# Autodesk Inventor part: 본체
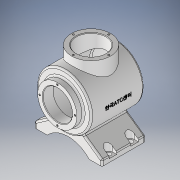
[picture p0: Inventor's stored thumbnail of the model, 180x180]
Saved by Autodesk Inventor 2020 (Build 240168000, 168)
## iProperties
Created: 2023-12
Part Number: 본체
Material: 일반
Document SubType Name: Modeling
Designer: 1강의실14
Density: 1 g/cm^3
Appearance: 기본값
Author: 1강의실14
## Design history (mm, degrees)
sketch "스케치1"
  geometry: L1 (50, 60)-(-50, 60); L2 (-50, 60)-(-50, -60); L3 (-50, -60)-(50, -60); L4 (50, -60)-(50, 60); L5 (50, 60)-(-50, -60); L6 (-50, 60)-(50, -60); L7 (0, 60)-(0, -60); L8 (0, 60)-(36, 60); L9 (36, 60)-(36, 48); L10 (36, 48)-(50, 48); L11 (36, 48)-(-16.182, 48); A1 r 113 centre (0, 53) between (-50, -48.336) and (50, -48.336); 3 further points
  constraints: 22 end point, 6 midpoint, 4 point on line, 3 perpendicular, 3 point on circle, 2 horizontal, 2 parallel, 1 centre point, 1 tangent, 1 vertical alignment
  dimensions: "d0" = 100 distance of L3.end L2.end; "d1" = 120 distance of L2.end L1.end; "d2" = 113 radius of A1; "d3" = 36 distance of L7.start L8.end; "d4" = 12 distance of L8.end L9.end
revolve "회전1" sketch "스케치1" stored, may be unused: angle "d5" = 90 deg
sketch "스케치2"
  geometry: 1 further point
feature "쉘1" dims "d9" = 7
sketch "스케치3"
  geometry: C1 r 36 at (0, 0); 1 further point
  constraints: 1 centre point, 1 coincident
  dimensions: "d10" = 72 diameter of C1
extrude "돌출1" join sketch "스케치3" distance "d11" = 12; taper "d12" = 0 deg
sketch "스케치4"
  geometry: C1 r 27 at (0, 0); 1 further point
  constraints: 1 centre point, 1 coincident
  dimensions: "d13" = 54 diameter of C1
extrude "돌출2" cut sketch "스케치4" distance "d14" = 19; taper "d15" = 0 deg
node "작업 평면2"
sketch "스케치7"
  geometry: L1 (36, 60)-(-36, 60) reference; C1 r 36 at (0, -2); C2 r 27 at (0, -2); 1 further point
  constraints: 2 centre point, 1 coincident, 1 vertical alignment
  dimensions: "d25" = 72 diameter of C1; "d26" = 54 diameter of C2; "d27" = 62 distance from line of L1 C1.centre
extrude "돌출5" join sketch "스케치7" stored distance "d28" = 19; taper "d29" = 0 deg
extrude "돌출6" cut sketch "스케치7" stored distance "d30" = 19; taper "d31" = 0 deg
node "작업 평면3"
sketch "스케치8"
  geometry: L1 (0, 0)-(0, -77); L2 (0, -77)-(-62, -77); L3 (-62, -77)-(-62, -67); L4 (-62, -67)-(-26.694, -42.278); L5 (62, -77)-(62, -67); L6 (62, -67)-(26.694, -42.278); L7 (62, -77)-(0, -77); L8 (0, -77)-(38.5, -77); L9 (0, -77)-(-38.5, -77); L10 (0, -60)-(22.364, -60); L11 (22.364, -60)-(16.943, -56.204); A1 r 52.096 centre (0, -112.096) between (38.5, -77) and (-38.5, -77); 2 further points
  constraints: 22 end point, 3 point on circle, 3 symmetric about line, 2 horizontal, 2 point on line, 2 vertical, 1 centre point, 3 other
  dimensions: "d33" = 77 distance of L1.start L1.end; "d38" = 62 distance of L1.end L2.end; "d39" = 10 distance of L2.end L3.end; "d40" = 55 deg angle of L3 L4; "d42" = 38.5 distance of L1.end L8.end; "d43" = 38.5 distance of L1.end L9.end; "d44" = 17 distance between parallel lines of L7 L10; "d45" = 52.09559 radius of A1
extrude "돌출7" join sketch "스케치8" distance "d46" = 80; taper "d47" = 0 deg
node "작업 평면4"
sketch "스케치10"
  geometry: L1 (-47, -20)-(-76.641, -20); L2 (-54, -13)-(-69.641, -13); L3 (-69.641, -27)-(-54, -27); L4 (-62, -40)-(-62, 40) reference; L5 (-38.5, -40)-(-62, -40) reference; A1 r 7 centre (-54, -20) between (-54, -27) and (-54, -13); A2 r 7 centre (-69.641, -20) between (-69.641, -13) and (-69.641, -27); 2 further points
  constraints: 8 end point, 6 point on circle, 4 tangent, 2 centre point, 2 point on line, 1 horizontal, 1 midpoint, 1 parallel
  dimensions: "d51" = 14 diameter of A2; "d52" = 8 distance from line of A1.centre L4; "d53" = 20 distance from line of A1.centre L5
extrude "돌출8" cut sketch "스케치10" distance "d54" = 20; taper "d55" = 0 deg
sketch "스케치12"
  geometry: L1 (0, 0)-(0, 20); L2 (0, 20)-(54, 20); L3 (62, -40)-(62, 40) reference
  constraints: 4 end point, 1 perpendicular, 1 vertical
  dimensions: "d59" = 20 distance of L1.start L1.end; "d60" = 8 distance from line of L2.end L3
hole "구멍1" sketch "스케치12" at (54, 20) diameter "d61" = 9; stored, may be unused: countersink angle "d65" = 90 deg, drill point angle "d67" = 118 deg; dims "d62" = 9, "d63" = 4, "d64" = 2, "d66" = 11
sketch "스케치13" dims "d74" = 65
  geometry: L1 (0, 0)-(0, 32.5); 1 further point
  constraints: 2 end point, 1 coincident, 1 vertical, 1 vertical alignment, 2 other
hole "구멍2" sketch "스케치13" at (0, 32.5) diameter "d75" = 3.242; stored, may be unused: countersink angle "d79" = 90 deg, drill point angle "d81" = 118 deg; dims "d76" = 8, "d77" = 4, "d78" = 2, "d80" = 10
sketch "스케치14" dims "d85" = 65
  geometry: L1 (0, 0)-(0, 32.5); C1 r 36 at (0, 0) reference; 1 further point
  constraints: 2 end point, 1 coincident, 1 vertical, 1 vertical alignment, 2 other
hole "구멍3" sketch "스케치14" at (0, 32.5) diameter "d86" = 3.242; stored, may be unused: countersink angle "d90" = 90 deg, drill point angle "d92" = 118 deg; dims "d87" = 8, "d88" = 4, "d89" = 2, "d91" = 10
feature "분할1"
fillet "모깎기1" dims "d96" = 3
chamfer "모따기1" distance "d97" = 1; stored, may be unused: second distance "d98" = 2, angle "d99" = 45 deg
node "작업 평면5"
sketch "스케치15"
  geometry: L1 (36, 60)-(-36, 60) reference; 2 further points
  constraints: 1 vertical alignment, 1 other
  dimensions: "d101" = 62 distance from line of point (0, -2) L1
feature "엠보싱1" sketch "스케치15" dims "d0" = 100, "d1" = 120, "d2" = 113, "d3" = 36, "d4" = 12, "d10" = 72, "d102" = 0.5, "d103" = 0
feature "분할2"
node "솔리드1"
pattern_linear "직사각형 패턴1" dims "d58" = 40
mirror "미러1"
pattern_linear "직사각형 패턴2" dims "d70" = 40, "d73" = 108
pattern_circular "원형 패턴1" dims angle "d83" = 360 deg
pattern_circular "원형 패턴2" dims angle "d94" = 360 deg
mirror "미러2"
feature "A9D066F2-1C7D-4E18-AEED-F7BC21143FA4" dims "d61" = 9, "d62" = 9, "d63" = 4, "d64" = 2, "d65" = 90 deg, "d66" = 11, "d67" = 118 deg
other parameters: "d24" = 65, "d50" = -71, "d100" = 56
